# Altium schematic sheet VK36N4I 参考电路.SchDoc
size A4; PageSetup: Record=PageOptions|CenterHorizontal=True|CenterVertical=True|PrintScale=1.00|XCorrection=1.00|YCorrection=1.00|PrintKind=0|BorderSize=5000000|LeftOffset=0|BottomOffset=0|Orientation=2|PaperLength=1000|PaperWidth=1000|Scale=100|PaperSource=7|PrintQuality=-4|MediaType=1|DitherType=10|PaperKind=A4|PrintScaleMode=1
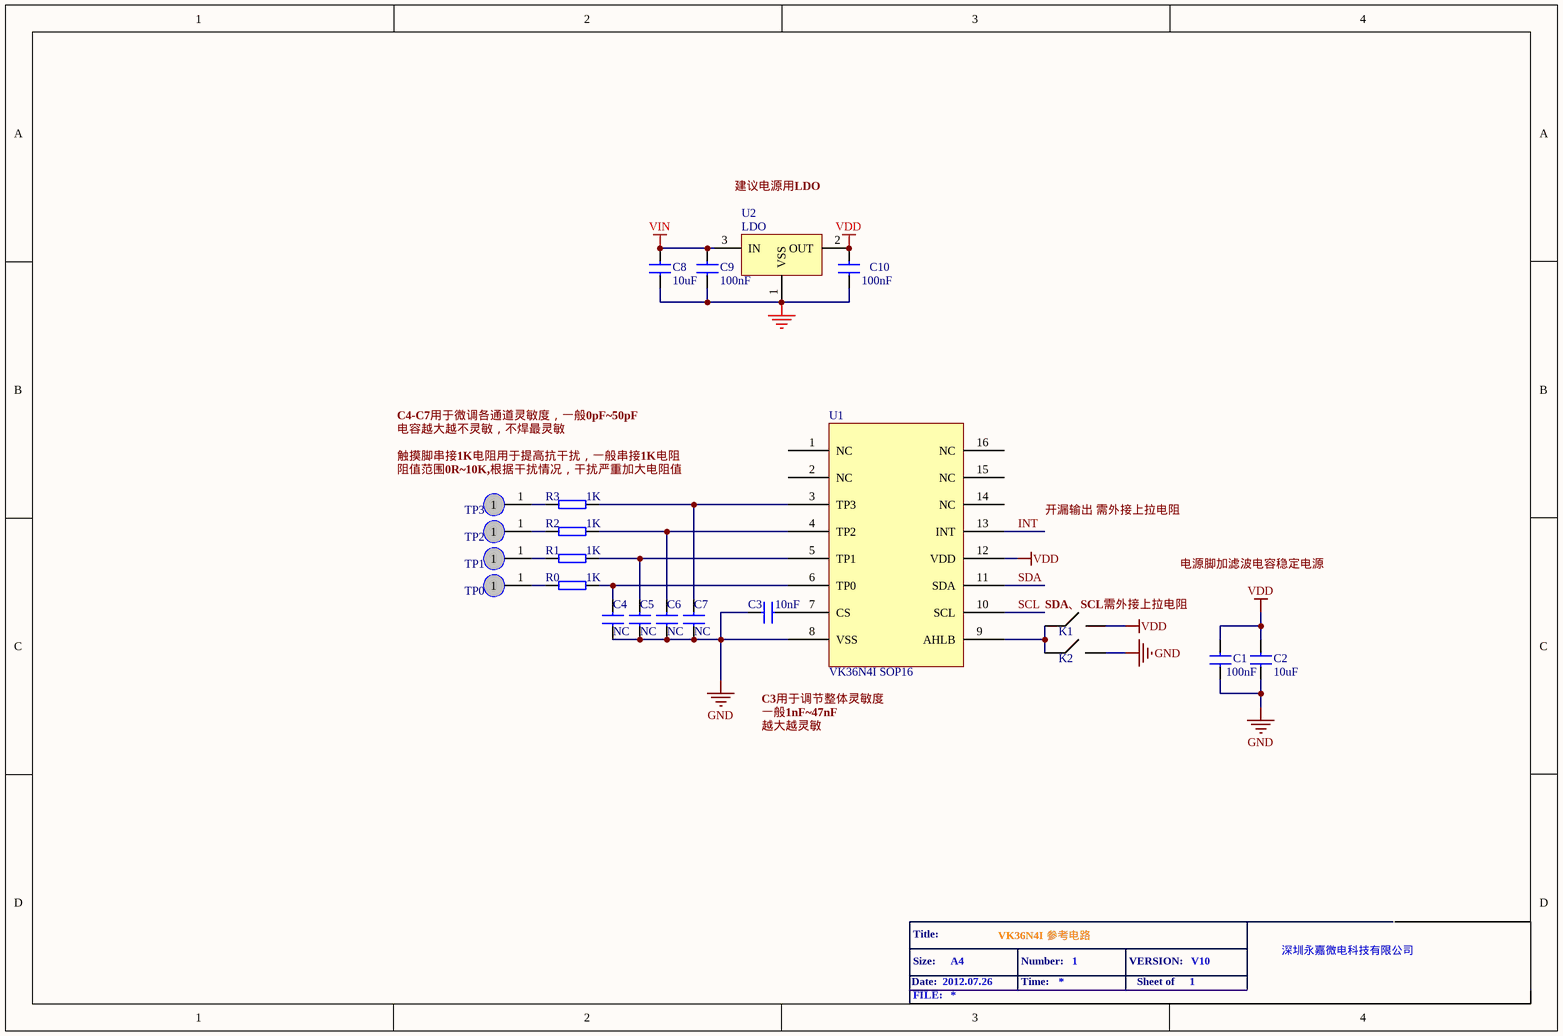
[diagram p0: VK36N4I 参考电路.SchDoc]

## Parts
C1  100nF  [0603-C]
C2  10uF  [0603-C]
C3  value 10nF  [0603-C]  (hidden comment: 10uF)
C4  value NC  [0603-C]  (hidden comment: 10uF)
C5  value NC  [0603-C]  (hidden comment: 10uF)
C6  value NC  [0603-C]  (hidden comment: 10uF)
C7  value NC  [0603-C]  (hidden comment: 10uF)
C8  10uF  [0805-C]
C9  100nF  [0805-C]
C10  100nF  [0805-C]
K1  单刀单掷开关  (value not drawn)
K2  单刀单掷开关  (value not drawn)
R0  1K  [0603-R]
R1  1K  [0603-R]
R2  1K  [0603-R]
R3  1K  [0603-R]
TP0  TPAD  [TP-PAD0]  (value not drawn)
TP1  TPAD  [TP-PAD0]  (value not drawn)
TP2  TPAD  [TP-PAD0]  (value not drawn)
TP3  TPAD  [TP-PAD0]  (value not drawn)
U1  VK36N4I SOP16
U2  LDO  [SOT-23]

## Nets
GND: C1.2 C2.2 C3.2 C4.1 C5.1 C6.1 C7.1 C8.2 C9.2 C10.2 U1.8(VSS) U2.1(VSS)
VDD: C1.1 C2.1 C10.1 U1.12(VDD) U2.2(OUT)
VIN: C8.1 C9.1 U2.3(IN)
INT: U1.13(INT)
SCL: U1.10(SCL)
SDA: U1.11(SDA)
NetC3_1: C3.1 U1.7(CS)
NetC4_2: C4.2 R0.2 U1.6(TP0)
NetC5_2: C5.2 R1.1 U1.5(TP1)
NetC6_2: C6.2 R2.1 U1.4(TP2)
NetC7_2: C7.2 R3.1 U1.3(TP3)
NetR0_1: R0.1 TP0.1
NetR1_2: R1.2 TP1.1
NetR2_2: R2.2 TP2.1
NetR3_2: R3.2 TP3.1

Not connected (* = marked no-connect by the designer): U1 1(NC) 2(NC) 9(AHLB) 14(NC) 15(NC) 16(NC)

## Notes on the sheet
- 建议电源用LDO
- C4-C7用于微调各通道灵敏度，一般0pF~50pF
- 电容越大越不灵敏，不焊最灵敏
- 触摸脚串接1K电阻用于提高抗干扰，一般串接1K电阻
- 阻值范围0R
  0K,根据干扰情况，干扰严重加大电阻值
- 开漏输出 需外接上拉电阻
- 电源脚加滤波电容稳定电源
- (near K1) SDA、SCL需外接上拉电阻
- C3用于调节整体灵敏度
- 一般1nF~47nF
- 越大越灵敏
- Date:
- Title:
- Size:
- 2012.07.26
- A4
- VK36N4I 参考电路
- Number:
- Time:
- 1
- VERSION:
- Sheet of
- V10
- 深圳永嘉微电科技有限公司
- FILE:

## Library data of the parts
C1-C10 = CAP: Capacitor
R0-R3 = RES: Resistor
TP0-TP3 = TPAD: TESTING
U2 = V6206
